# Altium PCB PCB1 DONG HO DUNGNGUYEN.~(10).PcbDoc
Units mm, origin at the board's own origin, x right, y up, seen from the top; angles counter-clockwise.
Board outline 60.96 x 45.72 mm, 2 copper layers (Top Layer, Bottom Layer); 84 components, 17 nets, 276 pads, 24 vias.
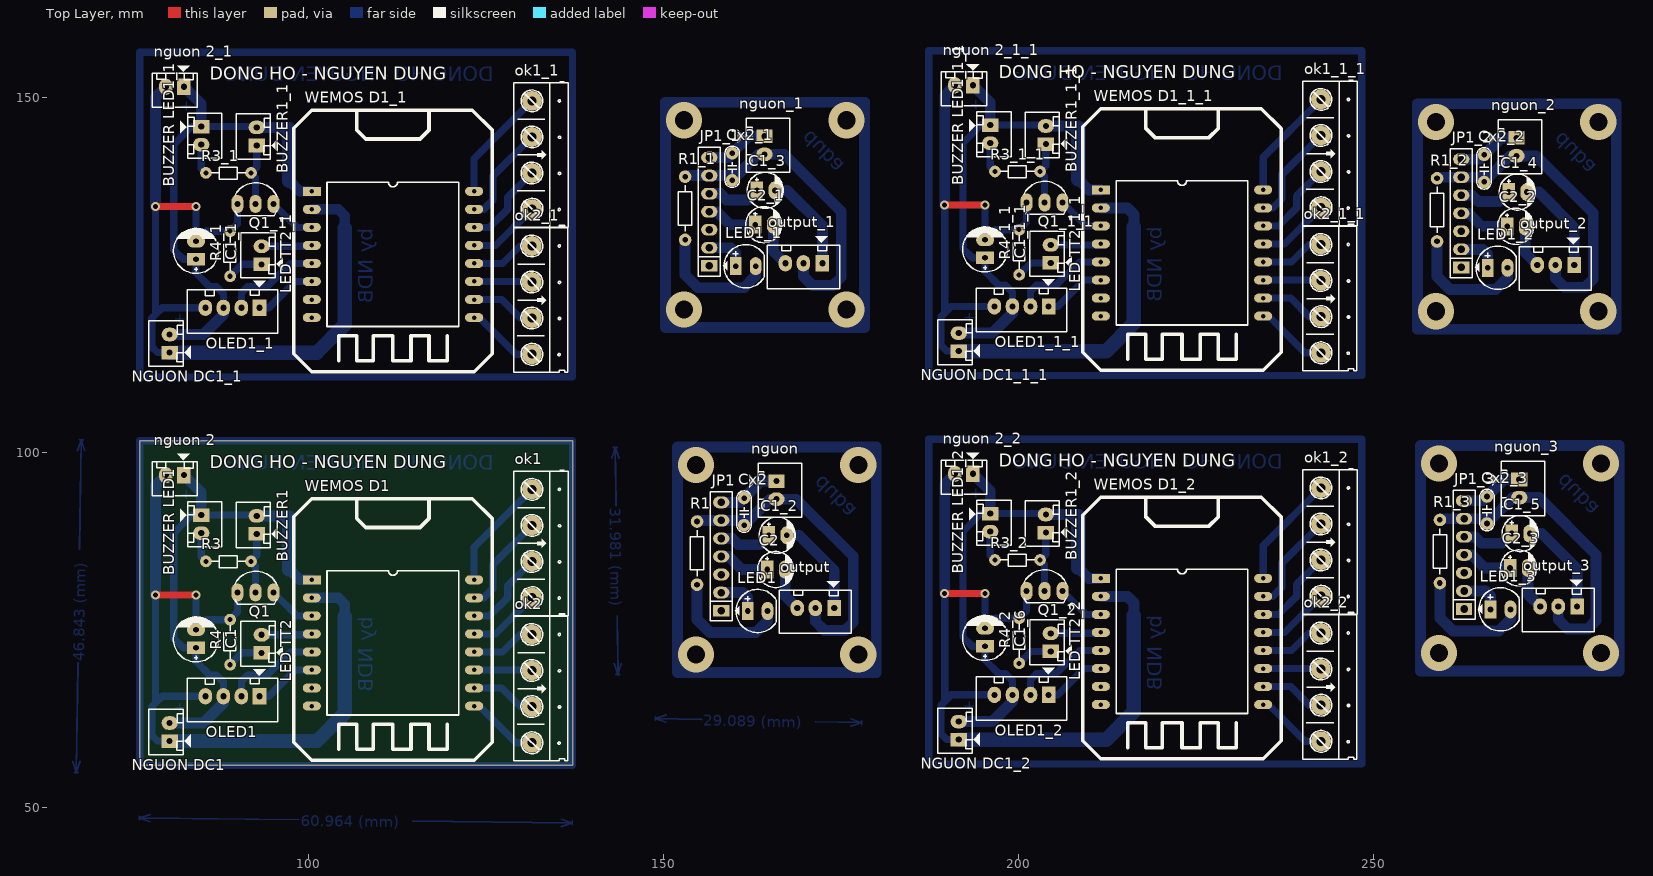
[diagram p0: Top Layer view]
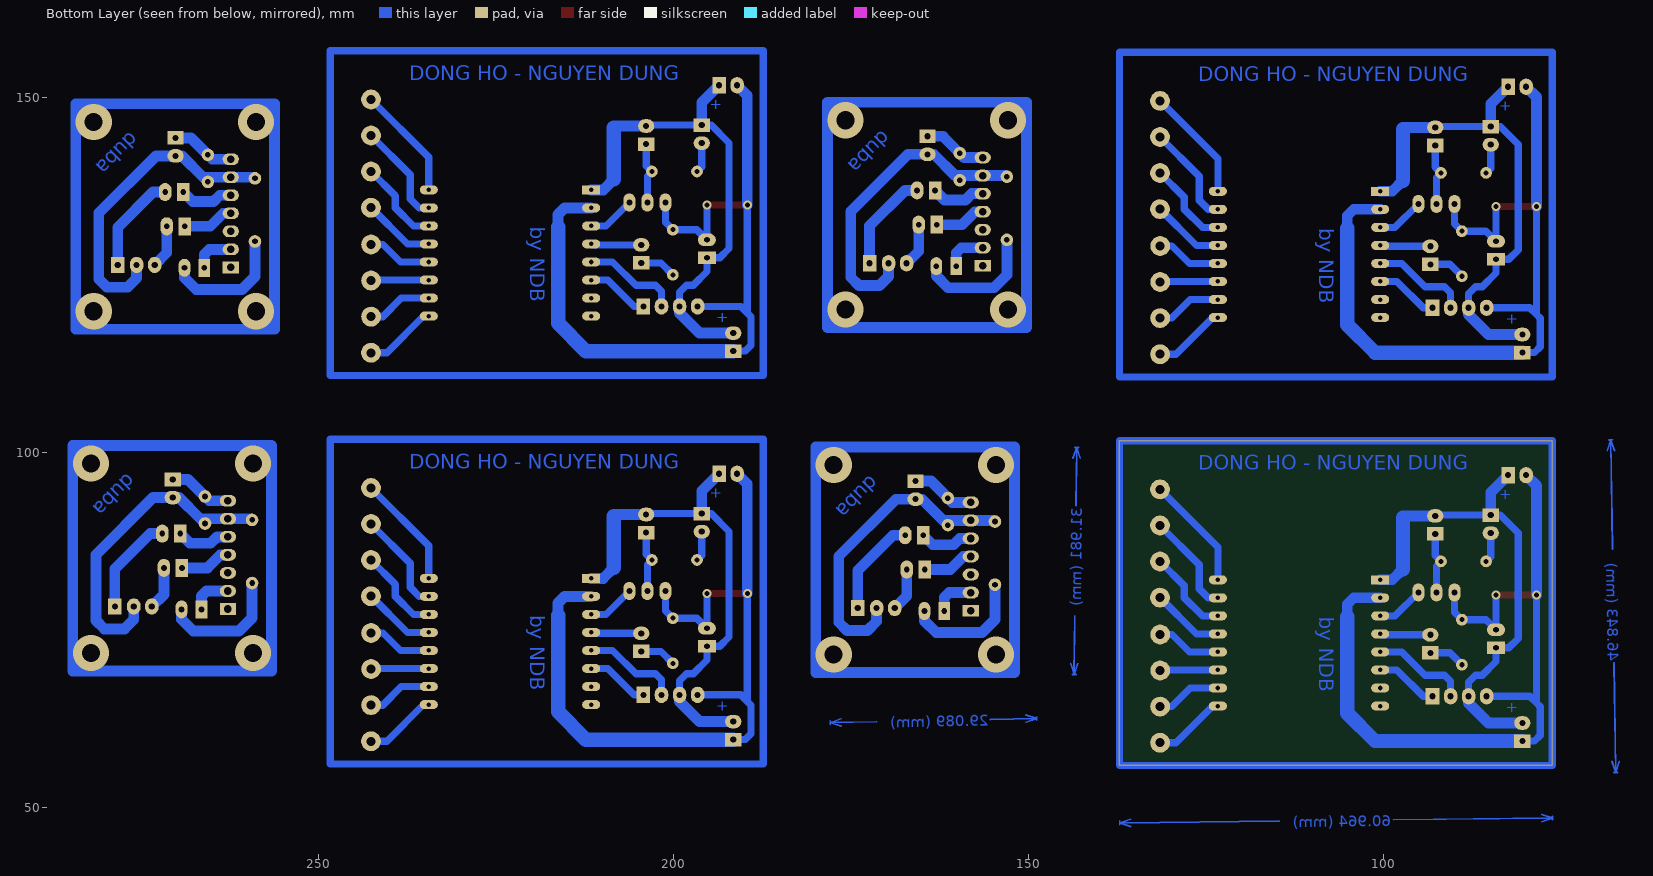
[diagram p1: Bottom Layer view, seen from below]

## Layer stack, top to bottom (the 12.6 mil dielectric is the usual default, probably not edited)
Top Solder: solder mask 0.0102, Solder Resist, Dk 3.5
Top Layer: signal copper 0.0356
Dielectric 1: dielectric 0.32, FR-4, Dk 4.8
Bottom Layer: signal copper 0.0356
Bottom Solder: solder mask 0.0102, Solder Resist, Dk 3.5

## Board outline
76.2,55.88 76.2,101.6 137.16,101.6 137.16,55.88

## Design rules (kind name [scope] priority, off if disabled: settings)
Clearance [All] p1: gap=0.254 ignorepadtopadclearanceinfootprint=FALSE except(0: Arc-Hole Track-Hole SMDPad-Hole THPad-Hole Via-Hole Fill-Hole Poly-Hole Region-Hole Text-Hole)
PolygonConnect [All] p1: connectstyle=Relief reliefconductorwidth=0.254 reliefentries=4 polygonreliefangle="90 Angle" airgapwidth=0.254
RoomDefinition DONG_HO [InComponentClass('DONG_HO')] p1: confinementstyle=ConfineIn formatcopy=TRUE lockcomponents=FALSE outline 138.303,57.277 149.25,57.277 149.25,67.132 138.303,67.132
RoutingVias [All] p1: holewidth=0.711 width=1.27 viastyle="Through Hole" minholewidth=0.711 minwidth=1.27 maxholewidth=2.54 maxwidth=2.54
SolderMaskExpansion [All] p1: expansion=0.102
Width [All] p1: maxlimit=2.032 minlimit=1.016 preferedwidth=1.524
30 further rules are at their usual default settings.

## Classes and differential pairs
component class DONG_HO: BUZZER1 "BUZZER LED1" C1 "LED TT2" "nguon 2" "NGUON DC1" ok1 ok2 OLED1 Q1 R3 R4 "WEMOS D1"

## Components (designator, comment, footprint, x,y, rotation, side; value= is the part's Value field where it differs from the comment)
BUZZER1 "Header2" Header2 92.685,88.468 r90 top
BUZZER1_1 "Header2" Header2 92.685,143.18 r90 top (schematic designator BUZZER1)
BUZZER1_1_1 "Header2" Header2 203.81,143.383 r90 top (schematic designator BUZZER1)
BUZZER1_2 "Header2" Header2 203.81,88.671 r90 top (schematic designator BUZZER1)
"BUZZER LED1" "Header2" Header2 84.861,91.135 r270 top
"BUZZER LED1_1" "Header2" Header2 84.861,145.847 r270 top (schematic designator "BUZZER LED1")
"BUZZER LED1_1_1" "Header2" Header2 195.986,146.05 r270 top (schematic designator "BUZZER LED1")
"BUZZER LED1_2" "Header2" Header2 195.986,91.338 r270 top (schematic designator "BUZZER LED1")
C1 "100uF" CP1/2.5 84.125,72.441 r90 top value="47uF/16 - 50V"
C1_1 "100uF" CP1/2.5 84.125,127.152 r90 top value="47uF/16 - 50V" (schematic designator C1)
C1_1_1 "100uF" CP1/2.5 195.25,127.356 r90 top value="47uF/16 - 50V" (schematic designator C1)
C1_2 "10uF" CP1/2 164.795,88.29 r0 top value=10uF/50V (schematic designator C1)
C1_3 "10uF" CP1/2 163.119,136.855 r0 top value=10uF/50V (schematic designator C1)
C1_4 "10uF" CP1/2 269.011,136.627 r0 top value=10uF/50V (schematic designator C1)
C1_5 "10uF" CP1/2 269.418,88.519 r0 top value=10uF/50V (schematic designator C1)
C1_6 "100uF" CP1/2.5 195.25,72.644 r90 top value="47uF/16 - 50V" (schematic designator C1)
C2 "10uF" CP1/2 164.567,83.464 r0 top value=10uF/50V
C2_1 "10uF" CP1/2 162.89,132.029 r0 top value=10uF/50V (schematic designator C2)
C2_2 "10uF" CP1/2 268.783,131.801 r0 top value=10uF/50V (schematic designator C2)
C2_3 "10uF" CP1/2 269.189,83.693 r0 top value=10uF/50V (schematic designator C2)
Cx2 "XXpF" CN1.5 161.315,91.491 r90 top value=33pF
Cx2_1 "XXpF" CN1.5 159.639,140.056 r90 top value=33pF (schematic designator Cx2)
Cx2_2 "XXpF" CN1.5 265.532,139.827 r90 top value=33pF (schematic designator Cx2)
Cx2_3 "XXpF" CN1.5 265.938,91.719 r90 top value=33pF (schematic designator Cx2)
JP1 "JP7 PIN" JP7 158.09,77.673 r90 top value=JP7
JP1_1 "JP7 PIN" JP7 156.413,126.238 r90 top value=JP7 (schematic designator JP1)
JP1_2 "JP7 PIN" JP7 262.306,126.009 r90 top value=JP7 (schematic designator JP1)
JP1_3 "JP7 PIN" JP7 262.712,77.902 r90 top value=JP7 (schematic designator JP1)
LED1 "LED" LED-5-BLUE 163.22,77.622 r0 top value="LED 3 ly Single Colour"
LED1_1 "LED" LED-5-BLUE 161.544,126.187 r0 top value="LED 3 ly Single Colour" (schematic designator LED1)
LED1_2 "LED" LED-5-BLUE 267.437,125.959 r0 top value="LED 3 ly Single Colour" (schematic designator LED1)
LED1_3 "LED" LED-5-BLUE 267.843,77.851 r0 top value="LED 3 ly Single Colour" (schematic designator LED1)
"LED TT2" "Header2" Header2 93.37,71.73 r90 top
"LED TT2_1" "Header2" Header2 93.37,126.441 r90 top (schematic designator "LED TT2")
"LED TT2_1_1" "Header2" Header2 204.495,126.644 r90 top (schematic designator "LED TT2")
"LED TT2_2" "Header2" Header2 204.495,71.933 r90 top (schematic designator "LED TT2")
nguon "JP2" CON2 165.862,95.91 r270 top value="Connector 2"
"nguon 2" "Header2" Header2 82.423,96.749 r180 top
"nguon 2_1" "Header2" Header2 82.423,151.46 r180 top (schematic designator "nguon 2")
"nguon 2_1_1" "Header2" Header2 193.548,151.663 r180 top (schematic designator "nguon 2")
"nguon 2_2" "Header2" Header2 193.548,96.952 r180 top (schematic designator "nguon 2")
"NGUON DC1" "Header2" Header2 80.416,59.309 r90 top
"NGUON DC1_1" "Header2" Header2 80.416,114.021 r90 top (schematic designator "NGUON DC1")
"NGUON DC1_1_1" "Header2" Header2 191.541,114.224 r90 top (schematic designator "NGUON DC1")
"NGUON DC1_2" "Header2" Header2 191.541,59.512 r90 top (schematic designator "NGUON DC1")
nguon_1 "JP2" CON2 164.186,144.475 r270 top value="Connector 2" (schematic designator nguon)
nguon_2 "JP2" CON2 270.078,144.247 r270 top value="Connector 2" (schematic designator nguon)
nguon_3 "JP2" CON2 270.485,96.139 r270 top value="Connector 2" (schematic designator nguon)
ok1 "Header 4" HED4 131.435,94.752 r270 top
ok1_1 "Header 4" HED4 131.435,149.464 r270 top (schematic designator ok1)
ok1_1_1 "Header 4" HED4 242.56,149.667 r270 top (schematic designator ok1)
ok1_2 "Header 4" HED4 242.56,94.955 r270 top (schematic designator ok1)
ok2 "Header 4" HED4 131.42,74.32 r270 top
ok2_1 "Header 4" HED4 131.42,129.032 r270 top (schematic designator ok2)
ok2_1_1 "Header 4" HED4 242.545,129.235 r270 top (schematic designator ok2)
ok2_2 "Header 4" HED4 242.545,74.524 r270 top (schematic designator ok2)
OLED1 "Header4" Header4 93.066,65.608 r180 top
OLED1_1 "Header4" Header4 93.066,120.32 r180 top (schematic designator OLED1)
OLED1_1_1 "Header4" Header4 204.191,120.523 r180 top (schematic designator OLED1)
OLED1_2 "Header4" Header4 204.191,65.811 r180 top (schematic designator OLED1)
output "JP3" CON3 173.888,78.029 r180 top value="Connector 3"
output_1 "JP3" CON3 172.212,126.594 r180 top value="Connector 3" (schematic designator output)
output_2 "JP3" CON3 278.105,126.365 r180 top value="Connector 3" (schematic designator output)
output_3 "JP3" CON3 278.511,78.257 r180 top value="Connector 3" (schematic designator output)
Q1 "C1815" QTO-92 92.507,80.239 r0 top
Q1_1 "C1815" QTO-92 92.507,134.95 r0 top (schematic designator Q1)
Q1_1_1 "C1815" QTO-92 203.632,135.153 r0 top (schematic designator Q1)
Q1_2 "C1815" QTO-92 203.632,80.442 r0 top (schematic designator Q1)
R1 "330" R1/4W 154.686,90.221 r270 top value="R1/4W - 1K"
R1_1 "330" R1/4W 153.01,138.786 r270 top value="R1/4W - 1K" (schematic designator R1)
R1_2 "330" R1/4W 258.902,138.557 r270 top value="R1/4W - 1K" (schematic designator R1)
R1_3 "330" R1/4W 259.309,90.449 r270 top value="R1/4W - 1K" (schematic designator R1)
R3 "100" RES-1/8W-SMALL 88.697,84.607 r180 top
R3_1 "100" RES-1/8W-SMALL 88.697,139.319 r180 top (schematic designator R3)
R3_1_1 "100" RES-1/8W-SMALL 199.822,139.522 r180 top (schematic designator R3)
R3_2 "100" RES-1/8W-SMALL 199.822,84.811 r180 top (schematic designator R3)
R4 "Res" RES-1/8W-SMALL 88.925,73.228 r90 top
R4_1 "Res" RES-1/8W-SMALL 88.925,127.94 r90 top (schematic designator R4)
R4_1_1 "Res" RES-1/8W-SMALL 200.05,128.143 r90 top (schematic designator R4)
R4_2 "Res" RES-1/8W-SMALL 200.05,73.431 r90 top (schematic designator R4)
"WEMOS D1" "Component_1" "ESP WEMOS MINI" 100.432,82.017 r0 top
"WEMOS D1_1" "Component_1" "ESP WEMOS MINI" 100.432,136.728 r0 top (schematic designator "WEMOS D1")
"WEMOS D1_1_1" "Component_1" "ESP WEMOS MINI" 211.557,136.931 r0 top (schematic designator "WEMOS D1")
"WEMOS D1_2" "Component_1" "ESP WEMOS MINI" 211.557,82.22 r0 top (schematic designator "WEMOS D1")

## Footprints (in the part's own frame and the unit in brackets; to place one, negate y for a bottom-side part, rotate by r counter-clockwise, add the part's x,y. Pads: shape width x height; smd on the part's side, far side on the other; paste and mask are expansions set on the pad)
CN1.5 [mil]
  round 70 hole 31: 1(-70,0) 2(80,0)
  silkscreen extent -110,-40 120,40, body extent -110,-33 120,33, height 235
CON2 [mil] "CON2"
  rect 75x90 hole 34: 1(0,0)
  oval 75x90 hole 34: 2(100,0)
  silkscreen extent -100,-150 200,140, body extent -68,-70 168,107, height 236
CON3 [mil] "CON 3"
  rect 75x90 hole 34: 1(-5,0)
  oval 75x90 hole 34: 2(100,0) 3(200,0)
  silkscreen extent -100,-150 300,140, body extent -95,-90 295,136, height 276
CP1/2 [mil] "Tu hoa < 22uF/16>50V"
  rect 70x100 hole 32: 1(0,0)
  oval 70x100 hole 32: 2(100,0)
  silkscreen extent -53,-100 147,100, body extent -49,-99 149,99, height 287
CP1/2.5 [mil] "Tu hoa 33 >100 uF,50V, 220uF/16V,25V"
  rect 70x100 hole 32: 1(0,0)
  oval 70x100 hole 32: 2(100,0)
  silkscreen extent -78,-125 172,125, body extent -76,-124 172,124, height 422
"ESP WEMOS MINI" [mm]
  rect 2.54x1.27 hole 0.635: 1(0,0)
  oval 2.54x1.27 hole 0.635: 2(0,-2.54) 3(0,-5.08) 4(0,-7.62) 5(0,-10.16) 6(0,-12.7) 7(0,-15.24) 8(0,-17.78) 9(22.86,-17.78) 10(22.86,-15.24) 11(22.86,-12.7) 12(22.86,-10.16) 13(22.86,-7.62) 14(22.86,-5.08) 15(22.86,-2.54) 16(22.86,0)
  silkscreen extent -2.54,-25.4 25.4,11.43
Header2 [mil] "CON2"
  rect 75x90 hole 34: 1(0,0)
  oval 75x90 hole 34: 2(100,0)
  silkscreen extent -75,-118 175,115, body extent -68,-70 168,107, height 236
Header4 [mil] "CON4"
  rect 75x90 hole 34: 1(0,0)
  oval 75x90 hole 34: 2(100,0) 3(200,0) 4(300,0)
  silkscreen extent -100,-150 400,140, body extent -90,-90 398,136, height 276
HED4 [mil] "Header 4, 4 pin, hight 300mil, Pin to Pin 200, Colour Green"
  round 110 hole 50: 1(0,0) 2(200,0) 3(400.06,0.06) 4(600.39,0.39)
  silkscreen extent -106,-100 700,200
JP7 [mil] "JP7"
  rect 65x90 hole 42: 1(0,0)
  oval 65x90 hole 42: 2(100,0) 3(200,0) 4(300,0) 5(400,0) 6(500,0) 7(600,0)
  silkscreen extent -57,-100 658,60, body extent -50,-49 646,49, height 323
LED-5-BLUE [mil] "LED 2 PIN, 5 ly , Only colour, pin to pin 110mil"
  rect 65x100 hole 32: 1(-55,0)
  oval 65x100 hole 32: 2(55,0)
  silkscreen extent -120,-120 104,120, body extent -113,-120 100,117, height 339
QTO-92 [mil] "TO-92"
  oval 66x100 hole 32: 1(-100,0) 2(0,0) 3(100,0)
  silkscreen extent -117,-65 120,118, body extent -109,-66 109,95, height 245
R1/4W [mil] "R 1/4W, 2 Pin, 350mil"
  round 70 hole 31: 1(0,0) 2(350,0)
  silkscreen extent 48,-38 302,38, body extent -40,-47 386,47, height 111
RES-1/8W-SMALL [mil] "R 1/8W, 2 pin, 200mil"
  round 65 hole 28: 1(-125,0) 2(125,0)
  silkscreen extent -95,-32 95,34, body extent -135,-35 135,37, height 76

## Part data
BUZZER1 BUZZER1_1 BUZZER1_1_1 BUZZER1_2 "BUZZER LED1" "BUZZER LED1_1" "BUZZER LED1_1_1" "BUZZER LED1_2" "LED TT2" "LED TT2_1" "LED TT2_1_1" "LED TT2_2" "nguon 2" "nguon 2_1" "nguon 2_1_1" "nguon 2_2" "NGUON DC1" "NGUON DC1_1" "NGUON DC1_1_1" "NGUON DC1_2": "Header IDC, 2 x 1 Pin Vertical 2.54mm Pitch (Non-Boxed, Male)", Manufacturer="Würth Elektronik eiSos GmbH", partNo=613002143121
C1 C1_1 C1_1_1 C1_6: library part CP2, "C 47uF/50V , 220uF/16V"
C1_2 C1_3 C1_4 C1_5 C2 C2_1 C2_2 C2_3: library part CP1, "Cap P  0,1uF < 22uF , 16 - 50V"
Cx2 Cx2_1 Cx2_2 Cx2_3: library part CN
JP1 JP1_1 JP1_2 JP1_3: library part JP7
LED1 LED1_1 LED1_2 LED1_3: "LED Single colour Green and Red"
nguon nguon_1 nguon_2 nguon_3: library part Con2, "Connector 2"
ok1 ok1_1 ok1_1_1 ok1_2 ok2 ok2_1 ok2_1_1 ok2_2: library part Hed4, "Header 4 (Green)"
OLED1 OLED1_1 OLED1_1_1 OLED1_2: "Header IDC, 4 x 1 Pin Vertical 2.54mm Pitch (Non-Boxed, Male)", Manufacturer="Würth Elektronik eiSos GmbH", partNo=613002143121
output output_1 output_2 output_3: library part Con3, "Connector 3"
Q1 Q1_1 Q1_1_1 Q1_2: "NPN 600mW, ECB"
R1 R1_1 R1_2 R1_3: library part R1/4W, "Resistor 1/4W"
R3 R3_1 R3_1_1 R3_2: library part Res, "Res", Manufacturer="Generic Components"
R4 R4_1 R4_1_1 R4_2: Manufacturer="Generic Components"

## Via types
v1: diameter 5.08, hole 2.54, Top Layer to Bottom Layer, 16 vias
v2: diameter 1.27, hole 0.711, Top Layer to Bottom Layer, 8 vias

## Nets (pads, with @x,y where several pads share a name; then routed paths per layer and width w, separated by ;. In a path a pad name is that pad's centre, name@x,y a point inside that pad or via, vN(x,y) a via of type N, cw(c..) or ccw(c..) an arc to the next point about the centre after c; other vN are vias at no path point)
D3: "LED TT2.2" "WEMOS D1.4" | length 7.1
  Bottom Layer w1.016: 93.37,74.27 100.305,74.27 100.432,74.397
D4: "WEMOS D1.3" Q1.3 | length 6.8
  Bottom Layer w1.016: Q1.3 98.349,76.937 100.432,76.937
GND: "nguon 2.2" "NGUON DC1.1" "WEMOS D1.2" C1.2 OLED1.4 Q1.1 R4.2 | length 114.6
  Top Layer w1.016: v2(78.435,79.883) v2(84.125,79.883)
  Bottom Layer w1.016: v2(78.435,79.883) 78.435,64.668 ; 80.416,59.309 78.715,59.309 77.902,60.122 77.902,64.135 78.435,64.668 ; v2(84.125,79.883) C1.2 85.547,76.403 R4.2 89.967,77.445 Q1.1 ; OLED1.4 79.375,65.608 78.435,64.668
  Bottom Layer w1.524: v2(78.435,79.883) 78.435,95.301 79.883,96.749 ; 100.432,79.477 104.165,79.477 105.08,78.562 105.08,76.784
  Bottom Layer w2.032: 80.416,59.309 101.168,59.309 105.08,63.221 105.08,76.784
NetBUZZER1_1: BUZZER1.1 Q1.2 R3.1 | length 8.8
  Bottom Layer w1.016: Q1.2 92.507,83.972 R3.1 92.685,85.42 BUZZER1.1
"NetBUZZER LED1_2": "BUZZER LED1.2" R3.2 | length 4.3
  Bottom Layer w1.016: 84.861,88.595 84.861,85.268 R3.2
"NetLED TT2_1": "LED TT2.1" R4.1 | length 5.1
  Bottom Layer w1.016: R4.1 90.602,71.73 93.37,71.73
Netok1_1: "WEMOS D1.16" ok1.1 | length 16.1
  Bottom Layer w1.016: 123.292,82.017 123.292,86.609 ok1.1
Netok1_2: "WEMOS D1.15" ok1.2 | length 14.4
  Bottom Layer w1.016: 123.292,79.477 124.638,79.477 125.908,80.747 125.908,84.145 ok1.2
Netok1_3: "WEMOS D1.14" ok1.3 | length 12.3
  Bottom Layer w1.016: 123.292,76.937 125.451,76.937 128.016,79.502 128.016,81.17 ok1.3
Netok1_4: "WEMOS D1.13" ok1.4 | length 10.3
  Bottom Layer w1.016: 123.292,74.397 126.289,74.397 131.394,79.502 ok1.4
Netok2_1: "WEMOS D1.12" ok2.1 | length 9.1
  Bottom Layer w1.016: 123.292,71.857 127.279,71.857 129.743,74.32 ok2.1
Netok2_2: "WEMOS D1.11" ok2.2 | length 8.2
  Bottom Layer w1.016: 123.292,69.317 131.343,69.317 ok2.2
Netok2_3: "WEMOS D1.10" ok2.3 | length 9.2
  Bottom Layer w1.016: 123.292,66.777 127.178,66.777 129.796,64.159 ok2.3
Netok2_4: "WEMOS D1.9" ok2.4 | length 10.3
  Bottom Layer w1.016: 123.292,64.237 124.028,64.237 129.194,59.07 ok2.4
SCL: "WEMOS D1.6" OLED1.1 | length 8.9
  Bottom Layer w1.016: OLED1.1 94.386,65.608 98.095,69.317 100.432,69.317
SDA: "WEMOS D1.5" OLED1.2 | length 13.7
  Bottom Layer w1.016: OLED1.2 90.526,67.742 91.364,68.58 94.132,68.58 97.409,71.857 100.432,71.857
VCC: "BUZZER LED1.1" "nguon 2.1" "NGUON DC1.2" "WEMOS D1.1" BUZZER1.2 C1.1 OLED1.3 | length 72.3
  Bottom Layer w1.016: OLED1.3 87.986,67.589 86.995,68.58 86.055,68.58 84.125,70.51 C1.1 82.321,72.441 81.001,73.762 81.001,88.621 83.515,91.135 84.861,91.135 92.558,91.135 BUZZER1.2
  Bottom Layer w1.524: 80.416,61.849 85.166,61.849 87.986,64.668 OLED1.3 ; 82.423,96.749 84.861,94.31 84.861,91.135 ; BUZZER1.2 96.977,91.008 97.218,90.767 ; 97.218,83.528 98.73,82.017 100.432,82.017
  Bottom Layer w2.032: 97.218,83.528 97.218,90.767
pads on no net: "BUZZER LED1_1.1" "BUZZER LED1_1.2" "BUZZER LED1_1_1.1" "BUZZER LED1_1_1.2" "BUZZER LED1_2.1" "BUZZER LED1_2.2" "LED TT2_1.1" "LED TT2_1.2" "LED TT2_1_1.1" "LED TT2_1_1.2" "LED TT2_2.1" "LED TT2_2.2" "nguon 2_1.1" "nguon 2_1.2" "nguon 2_1_1.1" "nguon 2_1_1.2" "nguon 2_2.1" "nguon 2_2.2" "NGUON DC1_1.1" "NGUON DC1_1.2" "NGUON DC1_1_1.1" "NGUON DC1_1_1.2" "NGUON DC1_2.1" "NGUON DC1_2.2" "WEMOS D1.7" "WEMOS D1.8" "WEMOS D1_1.1" "WEMOS D1_1.2" "WEMOS D1_1.3" "WEMOS D1_1.4" "WEMOS D1_1.5" "WEMOS D1_1.6" "WEMOS D1_1.7" "WEMOS D1_1.8" "WEMOS D1_1.9" "WEMOS D1_1.10" "WEMOS D1_1.11" "WEMOS D1_1.12" "WEMOS D1_1.13" "WEMOS D1_1.14" "WEMOS D1_1.15" "WEMOS D1_1.16" "WEMOS D1_1_1.1" "WEMOS D1_1_1.2" "WEMOS D1_1_1.3" "WEMOS D1_1_1.4" "WEMOS D1_1_1.5" "WEMOS D1_1_1.6" "WEMOS D1_1_1.7" "WEMOS D1_1_1.8" "WEMOS D1_1_1.9" "WEMOS D1_1_1.10" "WEMOS D1_1_1.11" "WEMOS D1_1_1.12" "WEMOS D1_1_1.13" "WEMOS D1_1_1.14" "WEMOS D1_1_1.15" "WEMOS D1_1_1.16" "WEMOS D1_2.1" "WEMOS D1_2.2" "WEMOS D1_2.3" "WEMOS D1_2.4" "WEMOS D1_2.5" "WEMOS D1_2.6" "WEMOS D1_2.7" "WEMOS D1_2.8" "WEMOS D1_2.9" "WEMOS D1_2.10" "WEMOS D1_2.11" "WEMOS D1_2.12" "WEMOS D1_2.13" "WEMOS D1_2.14" "WEMOS D1_2.15" "WEMOS D1_2.16" BUZZER1_1.1 BUZZER1_1.2 BUZZER1_1_1.1 BUZZER1_1_1.2 BUZZER1_2.1 BUZZER1_2.2 C1_1.1 C1_1.2 C1_1_1.1 C1_1_1.2 C1_2.1 C1_2.2 C1_3.1 C1_3.2 C1_4.1 C1_4.2 C1_5.1 C1_5.2 C1_6.1 C1_6.2 C2.1 C2.2 C2_1.1 C2_1.2 C2_2.1 C2_2.2 C2_3.1 C2_3.2 Cx2.1 Cx2.2 Cx2_1.1 Cx2_1.2 Cx2_2.1 Cx2_2.2 Cx2_3.1 Cx2_3.2 JP1.1 JP1.2 JP1.3 JP1.4 JP1.5 JP1.6 JP1.7 JP1_1.1 JP1_1.2 JP1_1.3 JP1_1.4 JP1_1.5 JP1_1.6 JP1_1.7 JP1_2.1 JP1_2.2 JP1_2.3 JP1_2.4 JP1_2.5 JP1_2.6 JP1_2.7 JP1_3.1 JP1_3.2 JP1_3.3 JP1_3.4 JP1_3.5 JP1_3.6 JP1_3.7 LED1.1 LED1.2 LED1_1.1 LED1_1.2 LED1_2.1 LED1_2.2 LED1_3.1 LED1_3.2 nguon.1 nguon.2 nguon_1.1 nguon_1.2 nguon_2.1 nguon_2.2 nguon_3.1 nguon_3.2 ok1_1.1 ok1_1.2 ok1_1.3 ok1_1.4 ok1_1_1.1 ok1_1_1.2 ok1_1_1.3 ok1_1_1.4 ok1_2.1 ok1_2.2 ok1_2.3 ok1_2.4 ok2_1.1 ok2_1.2 ok2_1.3 ok2_1.4 ok2_1_1.1 ok2_1_1.2 ok2_1_1.3 ok2_1_1.4 ok2_2.1 ok2_2.2 ok2_2.3 ok2_2.4 OLED1_1.1 OLED1_1.2 OLED1_1.3 OLED1_1.4 OLED1_1_1.1 OLED1_1_1.2 OLED1_1_1.3 OLED1_1_1.4 OLED1_2.1 OLED1_2.2 OLED1_2.3 OLED1_2.4 output.1 output.2 output.3 output_1.1 output_1.2 output_1.3 output_2.1 output_2.2 output_2.3 output_3.1 output_3.2 output_3.3 Q1_1.1 Q1_1.2 Q1_1.3 Q1_1_1.1 Q1_1_1.2 Q1_1_1.3 Q1_2.1 Q1_2.2 Q1_2.3 R1.1 R1.2 R1_1.1 R1_1.2 R1_2.1 R1_2.2 R1_3.1 R1_3.2 R3_1.1 R3_1.2 R3_1_1.1 R3_1_1.2 R3_2.1 R3_2.2 R4_1.1 R4_1.2 R4_1_1.1 R4_1_1.2 R4_2.1 R4_2.2
copper on no net: | length 2907.8
  Top Layer w1.016: v2(78.435,134.595) v2(84.125,134.595) ; v2(189.56,80.086) v2(195.25,80.086) ; v2(189.56,134.798) v2(195.25,134.798)
  Bottom Layer w0.254: 66.774,56.421 67.259,54.889 ; 67.005,54.893 67.513,54.886 ; 67.439,100.211 67.97,101.727 ; 67.493,70.285 67.259,54.889 ; 67.716,101.731 68.224,101.723 ; 67.737,86.331 67.97,101.727 ; 67.79,56.406 67.259,54.889 ; 68.455,100.195 67.97,101.727 ; 76.146,48.209 76.152,48.717 ; 77.667,47.938 76.149,48.463 ; 77.679,48.954 76.149,48.463 ; 98.606,48.211 76.149,48.463 ; 114.653,48.03 137.109,47.777 ; 135.58,47.287 137.109,47.777 ; 135.591,48.303 137.109,47.777 ; 137.106,47.523 137.112,48.031 ; 142.689,99.131 143.18,100.66 ; 142.926,100.657 143.434,100.663 ; 143.01,70.2 143.535,68.682 ; 143.271,92.44 143.18,100.66 ; 143.281,68.679 143.789,68.684 ; 143.444,76.901 143.535,68.682 ; 143.705,99.142 143.18,100.66 ; 144.026,70.211 143.535,68.682 ; 148.788,62.23 148.798,62.738 ; 150.307,61.945 148.793,62.484 ; 150.327,62.961 148.793,62.484 ; 155.312,62.353 148.793,62.484 ; 171.357,62.031 177.876,61.9 ; 176.342,61.423 177.876,61.9 ; 176.363,62.438 177.876,61.9 ; 177.871,61.646 177.881,62.154
  Bottom Layer w1.016: v2(78.435,134.595) 78.435,119.38 ; 80.416,114.021 78.715,114.021 77.902,114.833 77.902,118.847 78.435,119.38 ; v2(84.125,134.595) 84.125,129.692 85.547,131.115 88.925,131.115 89.967,132.156 89.967,134.95 ; 84.861,143.307 84.861,139.979 85.522,139.319 ; 85.446,120.32 79.375,120.32 78.435,119.38 ; 87.986,120.32 87.986,122.301 86.995,123.292 86.055,123.292 84.125,125.222 84.125,127.152 82.321,127.152 81.001,128.473 81.001,143.332 83.515,145.847 84.861,145.847 92.558,145.847 92.685,145.72 ; 88.925,124.765 90.602,126.441 93.37,126.441 ; 90.526,120.32 90.526,122.453 91.364,123.292 94.132,123.292 97.409,126.568 100.432,126.568 ; 92.507,134.95 92.507,138.684 91.872,139.319 92.685,140.132 92.685,143.18 ; 93.066,120.32 94.386,120.32 98.095,124.028 100.432,124.028 ; 93.37,128.981 100.305,128.981 100.432,129.108 ; 95.047,134.95 98.349,131.648 100.432,131.648 ; 123.292,118.948 124.028,118.948 129.194,113.782 131.43,113.782 ; 123.292,121.488 127.178,121.488 129.796,118.87 131.421,118.87 ; 123.292,124.028 131.343,124.028 131.42,123.952 ; 123.292,126.568 127.279,126.568 129.743,129.032 131.42,129.032 ; 123.292,129.108 126.289,129.108 131.394,134.214 131.445,134.214 ; 123.292,131.648 125.451,131.648 128.016,134.214 128.016,135.881 131.437,139.302 ; 123.292,134.188 124.638,134.188 125.908,135.458 125.908,138.856 131.435,144.384 ; 123.292,136.728 123.292,141.32 131.435,149.464 ; v2(189.56,80.086) 189.56,64.872 ; v2(189.56,134.798) 189.56,119.583 ; 191.541,59.512 189.84,59.512 189.027,60.325 189.027,64.338 189.56,64.872 ; 191.541,114.224 189.84,114.224 189.027,115.037 189.027,119.05 189.56,119.583 ; v2(195.25,80.086) 195.25,75.184 196.672,76.606 200.05,76.606 201.092,77.648 201.092,80.442 ; v2(195.25,134.798) 195.25,129.896 196.672,131.318 200.05,131.318 201.092,132.359 201.092,135.153 ; 195.986,88.798 195.986,85.471 196.647,84.811 ; 195.986,143.51 195.986,140.183 196.647,139.522 ; 196.571,65.811 190.5,65.811 189.56,64.872 ; 196.571,120.523 190.5,120.523 189.56,119.583 ; 199.111,65.811 199.111,67.793 198.12,68.783 197.18,68.783 195.25,70.714 195.25,72.644 193.446,72.644 192.126,73.965 192.126,88.824 194.64,91.338 195.986,91.338 203.683,91.338 203.81,91.211 ; 199.111,120.523 199.111,122.504 198.12,123.495 197.18,123.495 195.25,125.425 195.25,127.356 193.446,127.356 192.126,128.676 192.126,143.535 194.64,146.05 195.986,146.05 203.683,146.05 203.81,145.923 ; 200.05,70.256 201.727,71.933 204.495,71.933 ; 200.05,124.968 201.727,126.644 204.495,126.644 ; 201.651,65.811 201.651,67.945 202.489,68.783 205.257,68.783 208.534,72.06 211.557,72.06 ; 201.651,120.523 201.651,122.657 202.489,123.495 205.257,123.495 208.534,126.771 211.557,126.771 ; 203.632,80.442 203.632,84.176 202.997,84.811 203.81,85.623 203.81,88.671 ; 203.632,135.153 203.632,138.887 202.997,139.522 203.81,140.335 203.81,143.383 ; 204.191,65.811 205.511,65.811 209.22,69.52 211.557,69.52 ; 204.191,120.523 205.511,120.523 209.22,124.231 211.557,124.231 ; 204.495,74.473 211.43,74.473 211.557,74.6 ; 204.495,129.184 211.43,129.184 211.557,129.311 ; 206.172,80.442 209.474,77.14 211.557,77.14 ; 206.172,135.153 209.474,131.851 211.557,131.851 ; 234.417,64.44 235.153,64.44 240.319,59.274 242.555,59.274 ; 234.417,66.98 238.303,66.98 240.921,64.362 242.546,64.362 ; 234.417,69.52 242.468,69.52 242.545,69.444 ; 234.417,72.06 238.404,72.06 240.868,74.524 242.545,74.524 ; 234.417,74.6 237.414,74.6 242.519,79.705 242.57,79.705 ; 234.417,77.14 236.576,77.14 239.141,79.705 239.141,81.373 242.562,84.794 ; 234.417,79.68 235.763,79.68 237.033,80.95 237.033,84.348 242.56,89.875 ; 234.417,82.22 234.417,86.812 242.56,94.955 ; 234.417,119.151 235.153,119.151 240.319,113.985 242.555,113.985 ; 234.417,121.691 238.303,121.691 240.921,119.074 242.546,119.074 ; 234.417,124.231 242.468,124.231 242.545,124.155 ; 234.417,126.771 238.404,126.771 240.868,129.235 242.545,129.235 ; 234.417,129.311 237.414,129.311 242.519,134.417 242.57,134.417 ; 234.417,131.851 236.576,131.851 239.141,134.417 239.141,136.085 242.562,139.505 ; 234.417,134.391 235.763,134.391 237.033,135.661 237.033,139.06 242.56,144.587 ; 234.417,136.931 234.417,141.523 242.56,149.667 ; 76.2,55.88 76.2,101.6 137.16,101.6 137.16,55.88 76.2,55.88 ; 76.2,110.592 137.16,110.592 137.16,156.312 76.2,156.312 76.2,110.592 ; 187.325,56.083 248.285,56.083 248.285,101.803 187.325,101.803 187.325,56.083 ; 187.325,110.795 187.325,156.515 248.285,156.515 248.285,110.795 187.325,110.795
  Bottom Layer w1.524: v2(78.435,134.595) 78.435,150.012 79.883,151.46 ; 80.416,116.561 85.166,116.561 87.986,119.38 87.986,120.32 ; 82.423,151.46 84.861,149.022 84.861,145.847 ; 92.685,145.72 96.977,145.72 97.218,145.478 ; 97.218,138.239 98.73,136.728 100.432,136.728 ; 100.432,134.188 104.165,134.188 105.08,133.274 105.08,131.496 ; 153.01,129.896 153.01,124.968 154.838,123.139 161.29,123.139 162.941,124.79 162.941,126.187 ; 153.01,138.786 153.162,138.938 156.413,138.938 160.299,138.938 163.297,141.935 164.186,141.935 166.954,141.935 175.006,133.883 175.006,124.612 173.838,123.444 170.967,123.444 169.672,124.739 169.672,126.594 ; 154.686,81.331 154.686,76.403 156.515,74.574 162.966,74.574 164.617,76.225 164.617,77.622 ; 154.686,90.221 154.838,90.373 158.09,90.373 161.976,90.373 164.973,93.37 165.862,93.37 168.631,93.37 176.682,85.319 176.682,76.048 175.514,74.879 172.644,74.879 171.348,76.175 171.348,78.029 ; 156.413,128.778 159.436,128.778 160.147,128.067 160.147,126.187 ; 156.413,133.858 157.48,133.858 159.309,132.029 162.89,132.029 ; 156.413,136.398 157.963,136.398 158.852,135.509 161.773,135.509 163.119,136.855 ; 156.413,141.478 159.029,141.478 159.639,142.088 162.027,144.475 164.186,144.475 ; 158.09,80.213 161.112,80.213 161.823,79.502 161.823,77.622 ; 158.09,85.293 159.156,85.293 160.985,83.464 164.567,83.464 ; 158.09,87.833 159.639,87.833 160.528,86.944 163.449,86.944 164.795,88.29 ; 158.09,92.913 160.706,92.913 161.315,93.523 163.703,95.91 165.862,95.91 ; 165.43,132.029 165.43,128.295 167.132,126.594 ; 165.659,136.855 167.361,136.855 172.339,131.877 172.339,126.594 ; 167.107,83.464 167.107,79.731 168.808,78.029 ; 167.335,88.29 169.037,88.29 174.015,83.312 174.015,78.029 ; v2(189.56,80.086) 189.56,95.504 191.008,96.952 ; v2(189.56,134.798) 189.56,150.216 191.008,151.663 ; 191.541,62.052 196.291,62.052 199.111,64.872 199.111,65.811 ; 191.541,116.764 196.291,116.764 199.111,119.583 199.111,120.523 ; 193.548,96.952 195.986,94.513 195.986,91.338 ; 193.548,151.663 195.986,149.225 195.986,146.05 ; 203.81,91.211 208.102,91.211 208.343,90.97 ; 203.81,145.923 208.102,145.923 208.343,145.682 ; 208.343,83.731 209.855,82.22 211.557,82.22 ; 208.343,138.443 209.855,136.931 211.557,136.931 ; 211.557,79.68 215.29,79.68 216.205,78.765 216.205,76.987 ; 211.557,134.391 215.29,134.391 216.205,133.477 216.205,131.699 ; 258.902,129.667 258.902,124.739 260.731,122.911 267.183,122.911 268.834,124.562 268.834,125.959 ; 258.902,138.557 259.055,138.709 262.306,138.709 266.192,138.709 269.189,141.707 270.078,141.707 272.847,141.707 280.899,133.655 280.899,124.384 279.73,123.215 276.86,123.215 275.565,124.511 275.565,126.365 ; 259.309,81.559 259.309,76.632 261.137,74.803 267.589,74.803 269.24,76.454 269.24,77.851 ; 259.309,90.449 259.461,90.602 262.712,90.602 266.598,90.602 269.596,93.599 270.485,93.599 273.253,93.599 281.305,85.547 281.305,76.276 280.137,75.108 277.266,75.108 275.971,76.403 275.971,78.257 ; 262.306,128.549 265.328,128.549 266.04,127.838 266.04,125.959 ; 262.306,133.629 263.373,133.629 265.201,131.801 268.783,131.801 ; 262.306,136.169 263.855,136.169 264.744,135.28 267.665,135.28 269.011,136.627 ; 262.306,141.249 264.922,141.249 265.532,141.859 267.919,144.247 270.078,144.247 ; 262.712,80.442 265.735,80.442 266.446,79.731 266.446,77.851 ; 262.712,85.522 263.779,85.522 265.608,83.693 269.189,83.693 ; 262.712,88.062 264.262,88.062 265.151,87.173 268.072,87.173 269.418,88.519 ; 262.712,93.142 265.328,93.142 265.938,93.751 268.326,96.139 270.485,96.139 ; 271.323,131.801 271.323,128.067 273.025,126.365 ; 271.551,136.627 273.253,136.627 278.232,131.648 278.232,126.365 ; 271.729,83.693 271.729,79.959 273.431,78.257 ; 271.958,88.519 273.66,88.519 278.638,83.541 278.638,78.257 ; 150.266,117.526 150.266,149.276 178.257,149.276 178.257,117.526 150.266,117.526 ; 151.943,68.961 151.943,100.711 179.934,100.711 179.934,68.961 151.943,68.961 ; 256.159,117.297 256.159,149.047 284.15,149.047 284.15,117.297 256.159,117.297 ; 256.565,69.19 256.565,100.94 284.556,100.94 284.556,69.19 256.565,69.19
  Bottom Layer w2.032: 80.416,114.021 101.168,114.021 105.08,117.932 105.08,131.496 ; 97.218,138.239 97.218,145.478 ; 191.541,59.512 212.293,59.512 216.205,63.424 216.205,76.987 ; 191.541,114.224 212.293,114.224 216.205,118.135 216.205,131.699 ; 208.343,83.731 208.343,90.97 ; 208.343,138.443 208.343,145.682
  other v1: 154.534,71.501 177.394,71.501 259.156,71.73 282.016,71.73 154.534,98.171 177.394,98.171 259.156,98.4 282.016,98.4 258.75,119.837 281.61,119.837 152.857,120.066 175.717,120.066 258.75,146.507 281.61,146.507 152.857,146.736 175.717,146.736

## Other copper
Bottom Layer:
  text "DONG HO - NGUYEN DUNG" at 237.16,152.4 h2.03
  text "DONG HO - NGUYEN DUNG" at 126.035,152.197 h2.03
  text "+" at 193.065,148.26 h1.52
  text "+" at 81.94,148.057 h1.52
  text "duba" at 170.637,145.466 h2.03 r135
  text "duba" at 276.53,145.237 h2.03 r135
  text "by NDB" at 220.116,131.724 h2.03 r90
  text "by NDB" at 108.991,131.521 h2.03 r90
  text "+" at 192.151,118.288 h1.52
  text "+" at 81.026,118.085 h1.52
  text "DONG HO - NGUYEN DUNG" at 237.16,97.688 h2.03
  text "DONG HO - NGUYEN DUNG" at 126.035,97.485 h2.03
  text "duba" at 276.936,97.13 h2.03 r135
  text "duba" at 172.314,96.901 h2.03 r135
  text "+" at 193.065,93.548 h1.52
  text "+" at 81.94,93.345 h1.52
  text "31.981 (mm)" at 142.36,92.176 h1.52 r270.64
  text "by NDB" at 220.116,77.013 h2.03 r90
  text "by NDB" at 108.991,76.81 h2.03 r90
  text "46.843 (mm)" at 68.411,70.525 h1.52 r89.13
  text "+" at 192.151,63.576 h1.52
  text "+" at 81.026,63.373 h1.52
  text "29.089 (mm)" at 155.548,61.434 h1.52 r358.85
  text "60.964 (mm)" at 98.849,47.294 h1.52 r359.36

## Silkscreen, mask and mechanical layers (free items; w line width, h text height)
Top Overlay:
  text "DONG HO - NGUYEN DUNG" at 197.206,152.654 h1.78
  text "DONG HO - NGUYEN DUNG" at 86.081,152.451 h1.78
  text "DONG HO - NGUYEN DUNG" at 197.206,97.942 h1.78
  text "DONG HO - NGUYEN DUNG" at 86.081,97.739 h1.78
